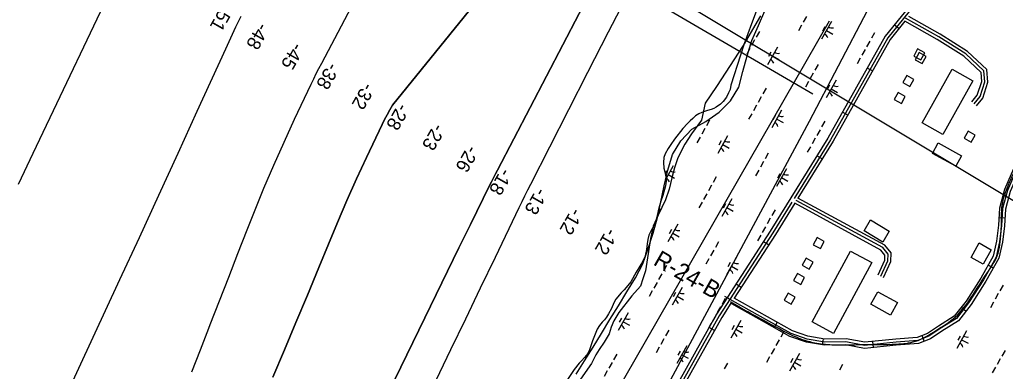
# Model space of a CAD drawing. Extents: x 3913936 to 3933962, y 195330 to 217741.
# Drawn here: x 3925651 to 3928086, y 206148 to 207016 of the extents above; entities that cross this region are included whole.
import ezdxf

# ---------------------------------------------------------------- set-up
doc = ezdxf.new("R2010")
doc.units = 0
for name, color, linetype in [('V-BLDG-OTLN', 7, 'Continuous'), ('V-RIVR-EDGE', 7, 'Continuous'), ('V-RIVR-RANG', 7, 'Continuous'), ('V-RIVR-RANG-IDEN', 7, 'Continuous'), ('V-ROAD-CNTR', 7, 'Continuous'), ('V-RRAP-FSHR', 7, 'Continuous'), ('V-TOPO-DPTH', 7, 'Continuous'), ('V-TOPO-MAJR', 7, 'Continuous'), ('V-TOPO-MINR', 7, 'Continuous'), ('V-UTIL-LINE', 7, 'Continuous'), ('V-WETL-SWMP', 7, 'Continuous')]:
    doc.layers.add(name, color=color, linetype=linetype)

msp = doc.modelspace()

# ---------------------------------------------------------------- linework, layer by layer
at = {"layer": 'V-BLDG-OTLN'}
for points in [[(3927869.4, 206944.2), (3927859.7, 206926.7), (3927877.2, 206917), (3927886.9, 206934.5)], [(3927873.1, 206935), (3927863.4, 206917.5), (3927880.9, 206907.8), (3927890.6, 206925.3)], [(3927842.5, 206878.7), (3927832.8, 206861.2), (3927850.3, 206851.5), (3927860, 206869)], [(3927880.6, 206761.8), (3927954.3, 206894), (3928005.6, 206865.5), (3927931.8, 206733.2)], [(3927821.4, 206836.6), (3927811.7, 206819.1), (3927829.2, 206809.4), (3927838.9, 206826.8)], [(3927994.1, 206741.2), (3927984.4, 206723.8), (3928001.9, 206714.1), (3928011.6, 206731.5)], [(3927963.6, 206654.5), (3927905.8, 206686.3), (3927920, 206712.2), (3927977.8, 206680.4)], [(3927783, 206467.1), (3927736.9, 206495.1), (3927753.2, 206521.9), (3927799.3, 206493.9)], [(3927621.2, 206478.2), (3927611.5, 206460.8), (3927629, 206451), (3927638.7, 206468.5)], [(3928001.4, 206429.1), (3928021.4, 206465.1), (3928051.2, 206448.5), (3928031.1, 206412.6)], [(3927608.8, 206270.4), (3927703.3, 206445.2), (3927755.9, 206416.8), (3927661.4, 206241.9)], [(3927593.8, 206427.7), (3927584.1, 206410.2), (3927601.6, 206400.5), (3927611.3, 206417.9)], [(3927572.7, 206389.7), (3927563, 206372.2), (3927580.5, 206362.5), (3927590.2, 206380)], [(3927549.5, 206341.2), (3927539.8, 206323.8), (3927557.3, 206314), (3927567, 206331.5)], [(3927770.8, 206344.6), (3927819.4, 206317.7), (3927802.5, 206287.1), (3927753.9, 206314.1)]]:
    msp.add_lwpolyline(points, close=True, dxfattribs=at)
at = {"layer": 'V-RIVR-EDGE'}
msp.add_lwpolyline([(3927481.4, 207025.6), (3927438.7, 206952.6), (3927372.4, 206851.5), (3927344.3, 206809.9), (3927335.3, 206768.4), (3927310.6, 206734.7), (3927293.8, 206708.8), (3927276.9, 206675.1), (3927269, 206650.4), (3927262.3, 206625.7), (3927255.6, 206597.6), (3927246.6, 206571.8), (3927228.6, 206533.6), (3927216.2, 206506.6), (3927209.5, 206476.3), (3927197.1, 206396.5), (3927190.4, 206376.3), (3927184.8, 206358.3), (3927163.4, 206334.7), (3927130.9, 206293.2), (3927118.5, 206272.9), (3927111.8, 206257.2), (3927107.3, 206240.4), (3927094.9, 206220.1), (3927082.6, 206202.2), (3927074.7, 206188.7), (3927063.5, 206167.3), (3927030.9, 206120.2)], dxfattribs=at)
at = {"layer": 'V-ROAD-CNTR'}
for p, q in [((3927823.2, 206994.3), (3927811.5, 207003.7)), ((3927757.8, 206889.7), (3927744.7, 206897)), ((3927696.5, 206780.7), (3927683.5, 206788)), ((3927633.3, 206672.5), (3927620.5, 206680.4)), ((3928085.3, 206526.6), (3928070.3, 206527.3)), ((3927501.2, 206460.1), (3927488.6, 206468.2)), ((3928056.5, 206403), (3928043.4, 206410.4)), ((3927433.4, 206355.1), (3927420.8, 206363.2)), ((3927988.8, 206296.7), (3927977, 206306)), ((3927515.1, 206255.9), (3927522.5, 206269)), ((3927367.7, 206249.3), (3927354.7, 206256.7)), ((3927634.2, 206213.6), (3927636.6, 206228.5)), ((3927760.2, 206206.9), (3927758.6, 206221.8)), ((3927885.7, 206222.2), (3927880.3, 206236.3))]:
    msp.add_line(p, q, dxfattribs=at)
for points in [[(3927948.7, 207158.5), (3927934.4, 207140.6), (3927925.1, 207131.8), (3927922.2, 207128.6), (3927795.4, 206971.9), (3927653.9, 206720.1), (3927564.1, 206574.8)], [(3927918.1, 207135.4), (3927789.2, 206976.1), (3927647.4, 206723.9), (3927505.4, 206494.2), (3927372.8, 206288.9), (3927242.2, 206056.6), (3927148.6, 205893.5)], [(3928009.2, 206808.7), (3928023.5, 206826.5), (3928035.3, 206862.8), (3928033.2, 206889.8), (3927988.3, 206932.3), (3927921.5, 206974.1), (3927839.7, 207020.1)], [(3928015, 206804), (3928030.2, 206822.8), (3928042.9, 206861.9), (3928040.5, 206893.3), (3927992.9, 206938.2), (3927925.3, 206980.6), (3927847.5, 207024.3)], [(3927837.9, 207012.5), (3927801.6, 206967.6), (3927660.3, 206716.3), (3927573.6, 206575.9)], [(3928003.3, 206813.4), (3928016.8, 206830.1), (3928027.7, 206863.7), (3928026, 206886.3), (3927983.7, 206926.3), (3927917.6, 206967.7), (3927837.9, 207012.5)], [(3928249.6, 206884.3), (3928203.7, 206802.6), (3928154.5, 206722.7), (3928121.4, 206663.8), (3928091.2, 206594.8), (3928078.9, 206550), (3928076.9, 206508.1), (3928071.6, 206468.1), (3928063, 206429.9), (3928031.8, 206374.3), (3927995.4, 206317.3), (3927965, 206278.5), (3927925.1, 206253.5), (3927897.4, 206234.7), (3927870, 206224.3), (3927816, 206220.2), (3927738.4, 206212.2), (3927691.8, 206221.2), (3927639.7, 206220.3), (3927596.4, 206227.5), (3927556.8, 206241.2), (3927494.6, 206276.1), (3927419.4, 206318.4), (3927393.3, 206333.1)], [(3928256.2, 206880.7), (3928210.1, 206798.8), (3928160.9, 206718.9), (3928128.1, 206660.5), (3928098.2, 206592.3), (3928086.4, 206548.8), (3928084.3, 206507.5), (3928079, 206466.8), (3928070.1, 206427.2), (3928038.2, 206370.4), (3928001.5, 206312.9), (3927970.1, 206272.8), (3927929.2, 206247.2), (3927900.8, 206228), (3927871.6, 206216.9), (3927816.7, 206212.7), (3927738.1, 206204.6), (3927691.2, 206213.7), (3927639.2, 206212.8), (3927594.6, 206220.2), (3927553.7, 206234.3), (3927491, 206269.5), (3927415.7, 206311.8), (3927408.2, 206316.1)], [(3928243.1, 206888), (3928197.2, 206806.4), (3928148, 206726.5), (3928114.7, 206667.2), (3928084.1, 206597.3), (3928071.5, 206551.2), (3928069.4, 206508.8), (3928064.2, 206469.4), (3928055.9, 206432.6), (3928025.3, 206378.2), (3927989.3, 206321.6), (3927959.9, 206284.1), (3927921, 206259.8), (3927893.9, 206241.4), (3927868.3, 206231.7), (3927815.4, 206227.7), (3927738.7, 206219.8), (3927692.5, 206228.7), (3927640.3, 206227.9), (3927598.2, 206234.8), (3927559.8, 206248), (3927498.3, 206282.6), (3927416.3, 206328.7)], [(3927558.6, 206566.1), (3927511.7, 206490.2), (3927379.2, 206285), (3927248.7, 206052.9), (3927155.1, 205889.8)], [(3927565.7, 206563.2), (3927518.1, 206486.2), (3927416.3, 206328.7)], [(3927771.8, 206386.3), (3927788.1, 206422.8), (3927788.7, 206435.3), (3927778.8, 206447.6), (3927565.7, 206563.2)], [(3927778.6, 206383.2), (3927795.6, 206421), (3927796.4, 206437.8), (3927783.7, 206453.5), (3927569.3, 206569.7)], [(3927785.4, 206380.2), (3927803, 206419.2), (3927804, 206440.3), (3927788.6, 206459.4), (3927573.6, 206575.9)], [(3927408.2, 206316.1), (3927385.6, 206281.2), (3927255.2, 206049.2), (3927161.6, 205886.1)]]:
    msp.add_lwpolyline(points, dxfattribs=at)
msp.add_spline([(3927406.7, 206320.8), (3927451.3, 206294.7), (3927529.1, 206252.7), (3927582.7, 206227.7), (3927615.4, 206218.6), (3927657.4, 206213.9), (3927733.9, 206214.2), (3927816.9, 206215.3), (3927864.1, 206222.2), (3927914.9, 206249), (3927962.8, 206282.6), (3927996, 206321.9), (3928040.1, 206389.8), (3928068.5, 206440), (3928073.4, 206468.8), (3928076.2, 206505), (3928078.4, 206558.1), (3928093.7, 206608.5), (3928118.5, 206661), (3928167.5, 206747.2), (3928247.9, 206882.7)], degree=3, dxfattribs=at)
at = {"layer": 'V-RRAP-FSHR'}
msp.add_lwpolyline([(3927025.8, 206140.8), (3927046.6, 206173.7), (3927067.7, 206207.7), (3927088.5, 206241.9), (3927109.3, 206276.4), (3927130.2, 206310.2), (3927151.3, 206344.1), (3927172.4, 206378.8), (3927190.3, 206413.6), (3927203.8, 206451.3), (3927215.7, 206489.5), (3927226.7, 206527.9), (3927235.3, 206567), (3927243.2, 206606.2), (3927251.9, 206645.2), (3927263.4, 206683.5), (3927284.2, 206716.9), (3927311.1, 206745.8), (3927346.3, 206764.9), (3927378.8, 206787.8), (3927406.7, 206816.1), (3927427.6, 206849.5), (3927437.7, 206888.2), (3927447.8, 206926.9), (3927460.1, 206964.9), (3927475.8, 207001.7), (3927491.6, 207038.4)], dxfattribs=at)
at = {"layer": 'V-TOPO-DPTH'}
for points in [[(3926076.2, 206147.1), (3926097.4, 206200.9), (3926118.4, 206254.8), (3926121.9, 206263.9), (3926144.5, 206322.3), (3926167.3, 206380.7), (3926190.2, 206439.1), (3926213.2, 206497.4), (3926230.9, 206542.4), (3926254.4, 206600.1), (3926278.6, 206657.4), (3926304, 206714.3), (3926330.1, 206770.8), (3926371.2, 206857.3), (3926377.5, 206870.3), (3926383.8, 206883.2), (3926390.3, 206896), (3926397, 206908.7), (3926649.3, 207388.2)], [(3926076.2, 206147.1), (3926097.4, 206200.9), (3926118.4, 206254.8), (3926121.9, 206263.9), (3926144.5, 206322.3), (3926167.3, 206380.7), (3926190.2, 206439.1), (3926213.2, 206497.4), (3926230.9, 206542.4), (3926254.4, 206600.1), (3926278.6, 206657.4), (3926304, 206714.3), (3926330.1, 206770.8), (3926371.2, 206857.3), (3926377.5, 206870.3), (3926383.8, 206883.2), (3926390.3, 206896), (3926397, 206908.7), (3926649.3, 207388.2)], [(3926276.5, 206133.4), (3926305.1, 206200.9), (3926333.5, 206268.6), (3926361.7, 206336.3), (3926389.7, 206404.1), (3926413.5, 206462), (3926436.1, 206516), (3926459.3, 206569.7), (3926483.3, 206623.1), (3926507.9, 206676.2), (3926546.2, 206757.4), (3926552.2, 206769.6), (3926558.5, 206781.7), (3926565.1, 206793.6), (3926571.9, 206805.4), (3926950.8, 207272.9)], [(3926950.8, 207272.9), (3926571.9, 206805.4), (3926565.1, 206793.6), (3926558.5, 206781.7), (3926552.2, 206769.6), (3926546.2, 206757.4), (3926507.9, 206676.2), (3926483.3, 206623.1), (3926459.3, 206569.7), (3926436.1, 206516), (3926413.5, 206462), (3926389.7, 206404.1), (3926361.7, 206336.3), (3926333.5, 206268.6), (3926305.1, 206200.9), (3926276.5, 206133.4)], [(3927073.3, 207110.1), (3926831.2, 206644.8), (3926826.4, 206635.4), (3926821.5, 206625.9), (3926816.8, 206616.4), (3926812, 206606.9), (3926764.5, 206510.9), (3926736.1, 206453.3), (3926707.8, 206395.7), (3926679.6, 206338.1), (3926651.5, 206280.4), (3926415.6, 205794.7)]]:
    msp.add_lwpolyline(points, dxfattribs=at)
at = {"layer": 'V-TOPO-MAJR'}
for points in [[(3925900.2, 207140.9), (3925683.3, 206686.1), (3925647.1, 206609.4)], [(3925639.7, 205787.3), (3925660.8, 205843.5), (3925683.3, 205899.2), (3925706.6, 205954.5), (3925743.2, 206038.6), (3925749, 206051.6), (3925754.7, 206064.6), (3925760.6, 206077.5), (3925766.5, 206090.4), (3925898.5, 206375.1), (3925946.6, 206478.9), (3925994.5, 206582.7), (3926042.2, 206686.7), (3926089.8, 206790.7), (3926160.1, 206944.5), (3926172.6, 206971.6), (3926185.3, 206998.5), (3926198.2, 207025.4)]]:
    msp.add_lwpolyline(points, dxfattribs=at)
at = {"layer": 'V-TOPO-MINR'}
for points in [[(3926076.2, 206147.1), (3926097.4, 206200.9), (3926118.4, 206254.8), (3926121.9, 206263.9), (3926144.5, 206322.3), (3926167.3, 206380.7), (3926190.2, 206439.1), (3926213.2, 206497.4), (3926230.9, 206542.4), (3926254.4, 206600.1), (3926278.6, 206657.4), (3926304, 206714.3), (3926330.1, 206770.8), (3926371.2, 206857.3), (3926377.5, 206870.3), (3926383.8, 206883.2), (3926390.3, 206896), (3926397, 206908.7), (3926649.3, 207388.2)], [(3926276.5, 206133.4), (3926305.1, 206200.9), (3926333.5, 206268.6), (3926361.7, 206336.3), (3926389.7, 206404.1), (3926413.5, 206462), (3926436.1, 206516), (3926459.3, 206569.7), (3926483.3, 206623.1), (3926507.9, 206676.2), (3926546.2, 206757.4), (3926552.2, 206769.6), (3926558.5, 206781.7), (3926565.1, 206793.6), (3926571.9, 206805.4), (3926950.8, 207272.9)], [(3926415.6, 205794.7), (3926651.5, 206280.4), (3926679.6, 206338.1), (3926707.8, 206395.7), (3926736.1, 206453.3), (3926764.5, 206510.9), (3926812, 206606.9), (3926816.8, 206616.4), (3926821.5, 206625.9), (3926826.4, 206635.4), (3926831.2, 206644.8), (3927073.3, 207110.1)], [(3926679.5, 206126.2), (3926716.3, 206202.1), (3926753, 206277.9), (3926789.6, 206353.9), (3926826.1, 206429.8), (3926885, 206552.9), (3926892, 206567.3), (3926899.1, 206581.7), (3926906.2, 206596.1), (3926913.5, 206610.4), (3927054.5, 206886.6), (3927105.4, 206986), (3927156.5, 207085.3)]]:
    msp.add_lwpolyline(points, dxfattribs=at)
at = {"layer": 'V-UTIL-LINE'}
for p, q in [((3924921.9, 208479.6), (3928401.9, 206392.2)), ((3925451.7, 208090.6), (3927610.8, 206833.3))]:
    msp.add_line(p, q, dxfattribs=at)
for points in [[(3922259.4, 198607.7), (3922481.8, 198996.5), (3922891.2, 199568.4), (3923401.9, 200205.9), (3924391.3, 201632.9), (3925141.5, 202100.5), (3925635.9, 202689.8), (3926060.6, 203224.6), (3926266.4, 203722.1), (3926398.8, 204373.1), (3926759.4, 205212), (3927229.5, 206070.8), (3927602.5, 206766.2), (3928031.8, 207586.2)], [(3927650.4, 207012.8), (3925143.7, 202648.2), (3924419.5, 201771.6), (3924393.5, 201817.6)]]:
    msp.add_lwpolyline(points, dxfattribs=at)
at = {"layer": 'V-WETL-SWMP'}
for p, q in [((3927594.4, 207024), (3927586.6, 207010.1)), ((3927582.6, 207003.1), (3927574.8, 206989.1)), ((3927656.3, 207011.7), (3927631.8, 206968.1)), ((3927640.3, 206998.9), (3927634.4, 206988.4)), ((3927478.4, 206987.2), (3927470.5, 206973.2)), ((3927644.1, 206989.9), (3927659.8, 206981)), ((3927762.9, 206984.3), (3927755.1, 206970.4)), ((3927454.9, 206945.3), (3927447, 206931.4)), ((3927466.6, 206966.3), (3927458.8, 206952.3)), ((3927523, 206948.7), (3927498.5, 206905.1)), ((3927751.2, 206963.4), (3927743.3, 206949.5)), ((3927506.9, 206935.9), (3927501, 206925.4)), ((3927510.7, 206926.9), (3927526.4, 206918.1)), ((3927727.6, 206921.6), (3927719.8, 206907.6)), ((3927739.4, 206942.5), (3927731.6, 206928.5)), ((3927623.4, 206905.7), (3927615.5, 206891.7)), ((3927611.6, 206884.7), (3927603.8, 206870.8)), ((3927494.9, 206847.1), (3927487.1, 206833.1)), ((3927599.9, 206863.8), (3927592, 206849.9)), ((3927668, 206867.2), (3927643.5, 206823.6)), ((3927651.9, 206854.4), (3927646, 206843.9)), ((3927483.2, 206826.2), (3927475.3, 206812.2)), ((3927655.7, 206845.4), (3927671.4, 206836.6)), ((3927471.4, 206805.2), (3927463.6, 206791.3)), ((3927459.7, 206784.3), (3927451.8, 206770.4)), ((3927533.4, 206792.9), (3927508.9, 206749.3)), ((3927517.3, 206780.1), (3927511.4, 206769.6)), ((3927355.4, 206768.4), (3927347.6, 206754.5)), ((3927521.1, 206771.1), (3927536.8, 206762.3)), ((3927639.9, 206765.6), (3927632.1, 206751.6)), ((3927331.9, 206726.6), (3927324, 206712.6)), ((3927343.6, 206747.5), (3927335.8, 206733.5)), ((3927400, 206729.9), (3927375.5, 206686.3)), ((3927628.2, 206744.7), (3927620.3, 206730.7)), ((3927384, 206717.2), (3927378.1, 206706.7)), ((3927387.7, 206708.1), (3927403.4, 206699.3)), ((3927604.7, 206702.8), (3927596.8, 206688.9)), ((3927616.4, 206723.7), (3927608.6, 206709.8)), ((3927500.4, 206686.9), (3927492.6, 206673)), ((3927265.4, 206655.6), (3927247.8, 206624.4)), ((3927488.6, 206666), (3927480.8, 206652)), ((3927249.3, 206642.9), (3927245.5, 206636)), ((3927253.1, 206633.8), (3927268.8, 206625)), ((3927372, 206628.3), (3927364.1, 206614.4)), ((3927476.9, 206645.1), (3927469, 206631.1)), ((3927545, 206648.4), (3927520.5, 206604.8)), ((3927528.9, 206635.6), (3927523.1, 206625.2)), ((3927360.2, 206607.4), (3927352.4, 206593.5)), ((3927532.7, 206626.6), (3927548.4, 206617.8)), ((3927348.5, 206586.5), (3927340.6, 206572.5)), ((3927336.7, 206565.6), (3927328.9, 206551.6)), ((3927410.4, 206574.1), (3927385.9, 206530.5)), ((3927394.3, 206561.4), (3927388.5, 206550.9)), ((3927232.4, 206549.7), (3927228, 206541.8)), ((3927398.1, 206552.3), (3927413.8, 206543.5)), ((3927517, 206546.8), (3927509.1, 206532.9)), ((3927277, 206511.2), (3927252.5, 206467.6)), ((3927505.2, 206525.9), (3927497.4, 206512)), ((3927261, 206498.4), (3927255.1, 206487.9)), ((3927264.8, 206489.4), (3927280.5, 206480.6)), ((3927481.7, 206484.1), (3927473.9, 206470.1)), ((3927493.5, 206505), (3927485.6, 206491)), ((3927377.4, 206468.1), (3927369.6, 206454.2)), ((3927365.7, 206447.2), (3927357.8, 206433.3)), ((3927249, 206409.6), (3927241.2, 206395.6)), ((3927353.9, 206426.3), (3927346.1, 206412.4)), ((3927422, 206429.7), (3927397.5, 206386.1)), ((3927406, 206416.9), (3927400.1, 206406.4)), ((3927237.2, 206388.6), (3927229.4, 206374.7)), ((3927409.8, 206407.9), (3927425.5, 206399.1)), ((3927225.5, 206367.7), (3927217.6, 206353.8)), ((3928080.4, 206360.9), (3928072.6, 206346.9)), ((3927213.7, 206346.8), (3927205.9, 206332.9)), ((3927287.4, 206355.4), (3927262.9, 206311.8)), ((3927271.4, 206342.6), (3927265.5, 206332.1)), ((3928068.6, 206340), (3928060.8, 206326)), ((3927275.2, 206333.6), (3927290.8, 206324.8)), ((3927394, 206328.1), (3927386.2, 206314.1)), ((3928056.9, 206319), (3928049, 206305.1)), ((3927154, 206292.4), (3927129.5, 206248.8)), ((3927382.2, 206307.1), (3927374.4, 206293.2)), ((3927138, 206279.6), (3927132.1, 206269.2)), ((3927141.8, 206270.6), (3927157.5, 206261.8)), ((3927358.7, 206265.3), (3927350.9, 206251.3)), ((3927370.5, 206286.2), (3927362.6, 206272.3)), ((3927432.4, 206273.9), (3927407.9, 206230.3)), ((3927254.5, 206249.4), (3927246.6, 206235.4)), ((3927416.4, 206261.1), (3927410.5, 206250.6)), ((3927420.2, 206252.1), (3927435.8, 206243.3)), ((3927539, 206246.6), (3927531.2, 206232.6)), ((3927990.4, 206248.1), (3927965.9, 206204.5)), ((3927242.7, 206228.5), (3927234.9, 206214.5)), ((3927527.2, 206225.6), (3927519.4, 206211.7)), ((3927974.3, 206235.3), (3927968.5, 206224.9)), ((3927978.1, 206226.3), (3927993.8, 206217.5)), ((3927126, 206190.8), (3927118.2, 206176.9)), ((3927230.9, 206207.5), (3927223.1, 206193.6)), ((3927299, 206210.9), (3927274.5, 206167.3)), ((3927283, 206198.1), (3927277.1, 206187.7)), ((3927515.5, 206204.7), (3927507.6, 206190.8)), ((3927577.4, 206192.4), (3927552.9, 206148.8)), ((3928085.2, 206199.9), (3928077.4, 206185.9)), ((3927114.3, 206169.9), (3927106.4, 206155.9)), ((3927286.8, 206189.1), (3927302.5, 206180.3)), ((3927399.5, 206167.9), (3927391.6, 206153.9)), ((3927503.7, 206183.8), (3927495.9, 206169.8)), ((3927561.4, 206179.6), (3927555.5, 206169.1)), ((3927565.2, 206170.6), (3927580.8, 206161.7)), ((3927684, 206165), (3927676.2, 206151.1)), ((3928073.4, 206178.9), (3928065.6, 206165)), ((3927102.5, 206149), (3927094.7, 206135)), ((3928061.7, 206158), (3928053.8, 206144.1))]:
    msp.add_line(p, q, dxfattribs=at)
for points in [[(3927492.7, 207096.8), (3927458.8, 207006.5), (3927440.4, 206956.6), (3927431.4, 206929), (3927408.1, 206854.5), (3927405.9, 206844.4), (3927402.1, 206835.4), (3927396.8, 206825.3), (3927389.2, 206814.6), (3927382.5, 206808.1), (3927371.5, 206800), (3927366.1, 206797.1), (3927358.9, 206794.5), (3927350.5, 206791.8), (3927343, 206789.7), (3927336.3, 206787.6), (3927328.4, 206783.6), (3927320.9, 206778.7), (3927313.8, 206772.7), (3927307.1, 206766.7), (3927300.7, 206760.2), (3927289.3, 206748), (3927268.9, 206721), (3927259.7, 206708.5), (3927252.9, 206698.4), (3927245.5, 206685.2), (3927242.5, 206676.4), (3927241.1, 206663.7), (3927242.2, 206649.8), (3927244.4, 206640.3), (3927247.6, 206628), (3927248.2, 206617.9), (3927247.2, 206611.2), (3927245.8, 206603.2), (3927244, 206596.8), (3927239.8, 206582.5), (3927235.3, 206568.1), (3927231.8, 206556.4), (3927228.5, 206544.3), (3927225.3, 206528.5), (3927222.1, 206517.2), (3927217.5, 206506.5), (3927211.2, 206496.2), (3927205.6, 206484), (3927202.6, 206473.9), (3927201.2, 206463.1), (3927199.8, 206448.6), (3927197.3, 206437.3), (3927195, 206431.1), (3927189.5, 206418.4), (3927174.3, 206393), (3927160.8, 206368.9), (3927153.7, 206359.8), (3927144, 206349.1), (3927136.9, 206341.6), (3927123.9, 206326)], [(3927123.9, 206326), (3927119, 206317.5), (3927112.7, 206303.2), (3927105.6, 206290.3), (3927100.3, 206282), (3927095.5, 206275.5), (3927089.6, 206269.2), (3927083.5, 206261.2), (3927077.6, 206252.1), (3927072.3, 206239.9), (3927066.3, 206223.1), (3927062, 206210.7), (3927059, 206200.9), (3927054.2, 206191.8), (3927046.3, 206182.5), (3927038.7, 206174.4), (3927033.3, 206167.9), (3927021.1, 206152.9), (3926981.7, 206094.2)]]:
    msp.add_lwpolyline(points, dxfattribs=at)
for centre, start, end in [((3927657.8, 207013.8), 239.8861, 281.4297), ((3927630.7, 206965.7), 19.8861, 61.4297), ((3927524.5, 206950.9), 239.8861, 281.4297), ((3927497.4, 206902.7), 19.8861, 61.4297), ((3927669.4, 206869.4), 239.8861, 281.4297), ((3927642.4, 206821.2), 19.8861, 61.4297), ((3927534.8, 206795.1), 239.8861, 281.4297), ((3927507.8, 206746.9), 19.8861, 61.4297), ((3927401.5, 206732.1), 239.8861, 281.4297), ((3927374.4, 206683.9), 19.8861, 61.4297), ((3927266.9, 206657.8), 239.8861, 281.4297), ((3927546.5, 206650.6), 239.8861, 281.4297), ((3927239.8, 206609.7), 19.8861, 61.4297), ((3927519.4, 206602.4), 19.8861, 61.4297), ((3927411.9, 206576.3), 239.8861, 281.4297), ((3927384.8, 206528.1), 19.8861, 61.4297), ((3927278.5, 206513.3), 239.8861, 281.4297), ((3927251.4, 206465.2), 19.8861, 61.4297), ((3927423.5, 206431.8), 239.8861, 281.4297), ((3927396.4, 206383.7), 19.8861, 61.4297), ((3927288.9, 206357.5), 239.8861, 281.4297), ((3927261.8, 206309.4), 19.8861, 61.4297), ((3927155.5, 206294.6), 239.8861, 281.4297), ((3927128.5, 206246.4), 19.8861, 61.4297), ((3927406.8, 206227.9), 19.8861, 61.4297), ((3927433.9, 206276), 239.8861, 281.4297), ((3927964.8, 206202.1), 19.8861, 61.4297), ((3927991.9, 206250.3), 239.8861, 281.4297), ((3927300.5, 206213.1), 239.8861, 281.4297), ((3927273.5, 206164.9), 19.8861, 61.4297), ((3927578.9, 206194.5), 239.8861, 281.4297), ((3927551.8, 206146.4), 19.8861, 61.4297)]:
    msp.add_arc(centre, 17.6, start, end, dxfattribs=at)

# ---------------------------------------------------------------- texts
at = {"layer": 'V-RIVR-RANG'}
for s, rotation, p in [('-51', 240.3202, (3926151.7, 207056.2)), ('-48', 240.3202, (3926241.3, 207011.3)), ('-45', 240.3202, (3926327.3, 206962)), ('-38', 240.3202, (3926414.3, 206913)), ('-32', 240.3202, (3926502, 206863.3)), ('-28', 240.3202, (3926587.2, 206812.3)), ('-23', 240.3202, (3926675.7, 206762.4)), ('-26', 240.1783, (3926758.7, 206708.6)), ('-18', 240.1783, (3926841.5, 206652)), ('-13', 240.1783, (3926929.1, 206603.7)), ('-12', 240.1783, (3927015.8, 206553.9)), ('-12', 240.1783, (3927102.7, 206504.4))]:
    msp.add_text(s, height=33.5, rotation=rotation, dxfattribs=at).set_placement(p)
at = {"layer": 'V-RIVR-RANG-IDEN'}
msp.add_text('R-24-B', height=41.5, rotation=330.3166, dxfattribs=at).set_placement((3927213.9, 206412.6))

doc.saveas('drawing.dxf')
